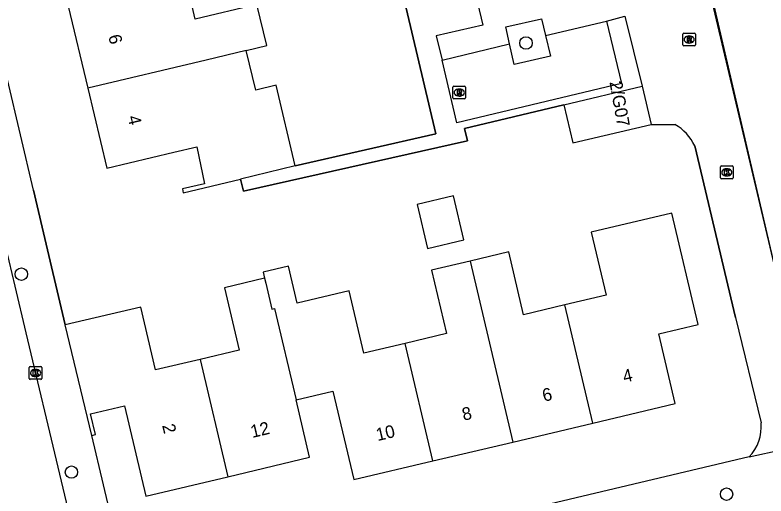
# Model space of a CAD drawing. Extents: x 157663 to 158496, y 379212 to 380934.
# Drawn here: x 158292.8 to 158352, y 380707 to 380744.9 of the extents above; entities that cross this region are included whole.
import ezdxf

# ---------------------------------------------------------------- set-up
doc = ezdxf.new("R2010")
doc.units = 0
for name, color, linetype in [('IMGEO_Boom', 7, 'Continuous'), ('IMGEO_Hek', 7, 'Continuous'), ('IMGEO_Kolk', 7, 'Continuous'), ('IMGEO_Muur', 7, 'Continuous'), ('IMGEO_Pand', 7, 'Continuous'), ('IMGEO_Pand_nummerreeks', 7, 'Continuous'), ('IMGEO_Parkeervlak_open', 7, 'Continuous'), ('IMGEO_Rijbaan_lokaal_open', 7, 'Continuous'), ('IMGEO_Rioolput', 7, 'Continuous'), ('IMGEO_Voetpad_open', 7, 'Continuous')]:
    doc.layers.add(name, color=color, linetype=linetype)

msp = doc.modelspace()

# ---------------------------------------------------------------- linework, layer by layer
at = {"layer": 'IMGEO_Boom'}
for centre in [(158333.093, 380742.662), (158293.329, 380724.463), (158297.276, 380708.882), (158348.899, 380707.141)]:
    msp.add_circle(centre, 0.489, dxfattribs=at)
at = {"layer": 'IMGEO_Hek'}
for points in [[(158314.918, 380732.983), (158325.994, 380735.514), (158319.98, 380760.991)], [(158336.076, 380737.805), (158328.253, 380735.93), (158328.489, 380734.953), (158310.833, 380731.012), (158310.609, 380731.957)], [(158342.945, 380736.243), (158344.828, 380736.26)], [(158349.611, 380721.053), (158346.384, 380734.559)], [(158294.286, 380731.078), (158294.972, 380728.159)], [(158294.972, 380728.159), (158296.795, 380720.47)]]:
    msp.add_lwpolyline(points, dxfattribs=at)
msp.add_arc((158342.872, 380732.909), 3.88, 25.16908, 59.73273, dxfattribs=at)
at = {"layer": 'IMGEO_Kolk'}
for p, q in [((158348.411, 380732.056), (158348.411, 380732.908)), ((158348.486, 380732.982), (158349.338, 380732.982)), ((158348.899, 380732.762), (158348.924, 380732.762)), ((158349.412, 380732.908), (158349.412, 380732.056)), ((158348.922, 380732.202), (158348.897, 380732.202)), ((158349.338, 380731.982), (158348.486, 380731.982)), ((158293.951, 380716.259), (158293.951, 380717.111)), ((158294.026, 380717.185), (158294.878, 380717.185)), ((158294.439, 380716.965), (158294.464, 380716.965)), ((158294.952, 380717.111), (158294.952, 380716.259)), ((158294.462, 380716.405), (158294.437, 380716.405)), ((158294.878, 380716.185), (158294.026, 380716.185))]:
    msp.add_line(p, q, dxfattribs=at)
for points in [[(158348.411, 380732.056), (158348.411, 380732.908)], [(158348.486, 380732.982), (158349.338, 380732.982)], [(158349.412, 380732.908), (158349.412, 380732.056)], [(158348.732, 380732.682), (158348.855, 380732.682), (158348.855, 380732.531), (158348.985, 380732.682), (158349.149, 380732.682), (158349.003, 380732.531), (158349.156, 380732.282), (158349.004, 380732.282), (158348.919, 380732.446), (158348.855, 380732.379), (158348.855, 380732.282), (158348.732, 380732.282), (158348.732, 380732.682)], [(158349.338, 380731.982), (158348.486, 380731.982)], [(158293.951, 380716.259), (158293.951, 380717.111)], [(158294.026, 380717.185), (158294.878, 380717.185)], [(158294.272, 380716.885), (158294.395, 380716.885), (158294.395, 380716.734), (158294.525, 380716.885), (158294.689, 380716.885), (158294.543, 380716.734), (158294.696, 380716.485), (158294.544, 380716.485), (158294.459, 380716.649), (158294.395, 380716.582), (158294.395, 380716.485), (158294.272, 380716.485), (158294.272, 380716.885)], [(158294.952, 380717.111), (158294.952, 380716.259)], [(158294.878, 380716.185), (158294.026, 380716.185)]]:
    msp.add_lwpolyline(points, dxfattribs=at)
for centre, start, end in [((158348.488, 380732.906), 91.55205, 178.44795), ((158348.488, 380732.906), 91.55205, 178.44795), ((158349.336, 380732.906), 1.55205, 88.44795), ((158349.336, 380732.906), 1.55205, 88.44795), ((158348.488, 380732.058), 181.55205, 268.44795), ((158348.488, 380732.058), 181.55205, 268.44795), ((158349.336, 380732.058), 271.55205, 358.44795), ((158349.336, 380732.058), 271.55205, 358.44795), ((158294.028, 380717.109), 91.55205, 178.44795), ((158294.028, 380717.109), 91.55205, 178.44795), ((158294.876, 380717.109), 1.55205, 88.44795), ((158294.876, 380717.109), 1.55205, 88.44795), ((158294.028, 380716.261), 181.55205, 268.44795), ((158294.028, 380716.261), 181.55205, 268.44795), ((158294.876, 380716.261), 271.55205, 358.44795), ((158294.876, 380716.261), 271.55205, 358.44795)]:
    msp.add_arc(centre, 0.0765, start, end, dxfattribs=at)
for centre, major_axis, ratio, start_param, end_param in [((158348.898, 380732.482), (-0.387, 0.002), 0.722429, 4.712389, 7.853982), ((158348.923, 380732.482), (-0.39, 0.002), 0.717154, 1.570796, 4.712389), ((158294.438, 380716.685), (-0.387, 0.002), 0.722429, 4.712389, 7.853982), ((158294.463, 380716.685), (-0.39, 0.002), 0.717154, 1.570796, 4.712389)]:
    msp.add_ellipse(centre, major_axis=major_axis, ratio=ratio, start_param=start_param, end_param=end_param, dxfattribs=at)
at = {"layer": 'IMGEO_Muur'}
msp.add_lwpolyline([(158346.181, 380752.523), (158353.297, 380722.372)], dxfattribs=at)
at = {"layer": 'IMGEO_Pand'}
for points in [[(158311.054, 380742.076), (158312.665, 380742.46), (158311.895, 380745.697), (158307.038, 380744.541), (158306.287, 380747.76)], [(158297.027, 380745.556), (158298.563, 380739.104)], [(158311.054, 380742.076), (158307.894, 380741.324), (158298.563, 380739.104)], [(158314.918, 380732.983), (158313.406, 380739.336), (158311.797, 380738.953), (158311.054, 380742.076)], [(158336.076, 380737.805), (158342.235, 380739.273)], [(158342.235, 380739.273), (158342.945, 380736.243)], [(158298.563, 380739.104), (158300.06, 380732.814), (158305.332, 380734.07), (158307.152, 380734.503), (158307.754, 380731.585), (158306.021, 380731.173), (158306.091, 380730.881), (158310.609, 380731.957)], [(158336.076, 380737.805), (158336.792, 380734.8), (158342.945, 380736.243)], [(158314.918, 380732.983), (158310.609, 380731.957)], [(158324.518, 380729.951), (158325.337, 380726.487), (158328.191, 380727.162), (158327.372, 380730.626), (158324.518, 380729.951)], [(158338.357, 380712.735), (158344.857, 380714.271), (158343.56, 380719.758), (158346.658, 380720.49), (158344.584, 380729.266), (158338.239, 380727.767), (158339.41, 380722.81), (158336.158, 380722.042)], [(158336.158, 380722.042), (158332.904, 380721.273), (158331.736, 380726.214), (158328.689, 380725.494)], [(158323.564, 380719.012), (158320.31, 380718.244), (158319.15, 380723.153), (158315.06, 380722.187), (158314.372, 380725.1), (158312.382, 380724.63), (158312.497, 380724.143)], [(158328.689, 380725.494), (158325.638, 380724.773), (158326.818, 380719.781), (158323.564, 380719.012)], [(158328.689, 380725.494), (158332.055, 380711.247)], [(158312.497, 380724.143), (158309.329, 380723.394), (158310.488, 380718.486), (158307.408, 380717.758)], [(158312.497, 380724.143), (158312.588, 380723.758), (158313.07, 380721.717), (158313.275, 380721.765), (158314.975, 380714.565)], [(158307.408, 380717.758), (158303.9, 380716.929), (158302.735, 380721.86), (158296.795, 380720.47)], [(158338.357, 380712.735), (158336.158, 380722.042)], [(158298.873, 380711.761), (158296.795, 380720.47)], [(158325.751, 380709.758), (158323.564, 380719.012)], [(158307.408, 380717.758), (158309.592, 380708.52)], [(158314.975, 380714.565), (158317.881, 380715.251), (158319.526, 380708.287), (158325.751, 380709.758)], [(158309.592, 380708.52), (158316.043, 380710.044), (158314.975, 380714.565)], [(158298.873, 380711.761), (158299.165, 380711.831), (158298.777, 380713.456), (158301.465, 380714.091), (158303.142, 380706.996), (158309.592, 380708.52)], [(158332.055, 380711.247), (158338.357, 380712.735)], [(158325.751, 380709.758), (158332.055, 380711.247)]]:
    msp.add_lwpolyline(points, dxfattribs=at)
at = {"layer": 'IMGEO_Parkeervlak_open'}
msp.add_lwpolyline([(158334.626, 380743.262), (158335.021, 380741.632), (158332.167, 380740.961), (158331.802, 380742.6)], dxfattribs=at)
at = {"layer": 'IMGEO_Rijbaan_lokaal_open'}
for points in [[(158299.078, 380697.367), (158299.024, 380697.594), (158293.7, 380719.842), (158292.832, 380723.522), (158291.886, 380727.513), (158290.986, 380731.308), (158286.732, 380749.252), (158285.857, 380752.928), (158285.387, 380754.879), (158284.513, 380758.542), (158281.657, 380770.677), (158280.79, 380774.351), (158280.032, 380777.559)], [(158347.448, 380747.566), (158353.297, 380722.372), (158355.983, 380711.227)], [(158329.261, 380745.828), (158329.69, 380744.059), (158326.028, 380743.217), (158326.478, 380741.304)], [(158339.435, 380744.397), (158340.886, 380744.769), (158342.235, 380739.273)], [(158331.802, 380742.6), (158331.505, 380743.933), (158334.311, 380744.565), (158334.626, 380743.262)], [(158334.626, 380743.262), (158339.435, 380744.397)], [(158326.478, 380741.304), (158331.802, 380742.6)], [(158342.945, 380736.243), (158344.828, 380736.26)], [(158346.384, 380734.559), (158349.611, 380721.053), (158351.618, 380712.754)], [(158350.686, 380710.073), (158355.983, 380711.227)]]:
    msp.add_lwpolyline(points, dxfattribs=at)
for centre, radius, start, end in [((158342.872, 380732.909), 3.88, 25.16908, 59.73273), ((158348.211, 380712.436), 3.422, 316.32652, 5.33536)]:
    msp.add_arc(centre, radius, start, end, dxfattribs=at)
at = {"layer": 'IMGEO_Rioolput'}
for p, q in [((158345.52, 380743.443), (158346.372, 380743.443)), ((158345.445, 380742.517), (158345.445, 380743.369)), ((158345.933, 380743.223), (158345.958, 380743.223)), ((158346.446, 380743.369), (158346.446, 380742.517)), ((158346.372, 380742.443), (158345.52, 380742.443)), ((158345.956, 380742.663), (158345.931, 380742.663)), ((158327.333, 380738.336), (158327.333, 380739.188)), ((158327.408, 380739.262), (158328.26, 380739.262)), ((158327.821, 380739.042), (158327.846, 380739.042)), ((158328.334, 380739.188), (158328.334, 380738.336)), ((158328.26, 380738.262), (158327.408, 380738.262)), ((158327.844, 380738.482), (158327.819, 380738.482))]:
    msp.add_line(p, q, dxfattribs=at)
for points in [[(158345.52, 380743.443), (158346.372, 380743.443)], [(158345.445, 380742.517), (158345.445, 380743.369)], [(158346.034, 380743.141), (158345.782, 380743.143), (158345.782, 380742.743)], [(158345.782, 380742.743), (158345.906, 380742.743), (158345.906, 380742.905), (158345.917, 380742.905)], [(158345.96, 380743.062), (158345.906, 380743.062), (158345.906, 380742.981)], [(158345.906, 380742.981), (158345.958, 380742.981)], [(158345.964, 380742.876), (158346.035, 380742.743), (158346.175, 380742.743), (158346.11, 380742.869)], [(158346.446, 380743.369), (158346.446, 380742.517)], [(158346.372, 380742.443), (158345.52, 380742.443)], [(158327.333, 380738.336), (158327.333, 380739.188)], [(158327.408, 380739.262), (158328.26, 380739.262)], [(158327.922, 380738.96), (158327.67, 380738.962), (158327.67, 380738.562)], [(158327.67, 380738.562), (158327.794, 380738.562), (158327.794, 380738.724), (158327.805, 380738.724)], [(158327.848, 380738.881), (158327.794, 380738.881), (158327.794, 380738.8)], [(158327.794, 380738.8), (158327.846, 380738.8)], [(158327.852, 380738.695), (158327.923, 380738.562), (158328.063, 380738.562), (158327.998, 380738.688)], [(158328.334, 380739.188), (158328.334, 380738.336)], [(158328.26, 380738.262), (158327.408, 380738.262)]]:
    msp.add_lwpolyline(points, dxfattribs=at)
for centre, radius, start, end in [((158345.522, 380743.367), 0.0765, 91.55205, 178.44795), ((158345.522, 380743.367), 0.0765, 91.55205, 178.44795), ((158346.37, 380743.367), 0.0765, 1.55205, 88.44795), ((158346.37, 380743.367), 0.0765, 1.55205, 88.44795), ((158345.916, 380742.852), 0.0533, 26.02933, 88.69889), ((158345.942, 380743.17), 0.19, 274.7715, 282.96867), ((158345.966, 380742.966), 0.0964, 77.00612, 93.18647), ((158345.98, 380743.023), 0.0378, 276.66336, 79.67722), ((158346.033, 380743.031), 0.109, 350.36119, 89.41601), ((158346.031, 380743.031), 0.112, 277.58423, 350.98172), ((158346.015, 380742.816), 0.108, 29.51342, 73.79051), ((158345.522, 380742.519), 0.0765, 181.55205, 268.44795), ((158345.522, 380742.519), 0.0765, 181.55205, 268.44795), ((158346.37, 380742.519), 0.0765, 271.55205, 358.44795), ((158346.37, 380742.519), 0.0765, 271.55205, 358.44795), ((158327.41, 380739.186), 0.0765, 91.55205, 178.44795), ((158327.41, 380739.186), 0.0765, 91.55205, 178.44795), ((158327.804, 380738.671), 0.0533, 26.02933, 88.69889), ((158327.83, 380738.989), 0.19, 274.7715, 282.96867), ((158327.854, 380738.785), 0.0964, 77.00612, 93.18647), ((158327.868, 380738.842), 0.0378, 276.66336, 79.67722), ((158327.921, 380738.85), 0.109, 350.36119, 89.41601), ((158327.919, 380738.85), 0.112, 277.58423, 350.98172), ((158327.903, 380738.635), 0.108, 29.51342, 73.79051), ((158328.258, 380739.186), 0.0765, 1.55205, 88.44795), ((158328.258, 380739.186), 0.0765, 1.55205, 88.44795), ((158327.41, 380738.338), 0.0765, 181.55205, 268.44795), ((158327.41, 380738.338), 0.0765, 181.55205, 268.44795), ((158328.258, 380738.338), 0.0765, 271.55205, 358.44795), ((158328.258, 380738.338), 0.0765, 271.55205, 358.44795)]:
    msp.add_arc(centre, radius, start, end, dxfattribs=at)
for centre, major_axis, ratio, start_param, end_param in [((158345.932, 380742.943), (-0.387, 0.002), 0.722429, 4.712389, 7.853982), ((158345.957, 380742.943), (-0.39, 0.002), 0.717154, 1.570796, 4.712389), ((158327.82, 380738.762), (-0.387, 0.002), 0.722429, 4.712389, 7.853982), ((158327.845, 380738.762), (-0.39, 0.002), 0.717154, 1.570796, 4.712389)]:
    msp.add_ellipse(centre, major_axis=major_axis, ratio=ratio, start_param=start_param, end_param=end_param, dxfattribs=at)
at = {"layer": 'IMGEO_Voetpad_open'}
for points in [[(158308.977, 380758.404), (158319.98, 380760.991), (158325.994, 380735.514), (158314.918, 380732.983)], [(158296.795, 380720.47), (158294.972, 380728.159), (158294.286, 380731.078), (158291.182, 380744.148), (158289.647, 380750.631), (158288.94, 380753.648)], [(158339.435, 380744.397), (158340.626, 380739.482), (158327.651, 380736.384), (158326.478, 380741.304)], [(158310.609, 380731.957), (158310.833, 380731.012), (158328.489, 380734.953), (158328.253, 380735.93), (158336.076, 380737.805)], [(158301.653, 380700.101), (158298.873, 380711.761)], [(158350.686, 380710.073), (158304.146, 380699.056)]]:
    msp.add_lwpolyline(points, dxfattribs=at)

# ---------------------------------------------------------------- texts
at = {"layer": 'IMGEO_Pand_nummerreeks'}
for s, rotation, p in [('6', 283.38981, (158300.174, 380743.214)), ('2/G07', 280.09765, (158339.666, 380739.588)), ('4', 283.38981, (158301.69, 380736.848)), ('4', 13.29144, (158340.843, 380715.912)), ('6', 13.29144, (158334.51, 380714.416)), ('8', 13.29144, (158328.181, 380712.921)), ('2', 283.29857, (158304.418, 380712.559)), ('12', 13.29262, (158311.52, 380711.565)), ('10', 13.29262, (158321.401, 380711.319))]:
    msp.add_text(s, height=1, rotation=rotation, dxfattribs=at).set_placement(p)

doc.saveas('drawing.dxf')
